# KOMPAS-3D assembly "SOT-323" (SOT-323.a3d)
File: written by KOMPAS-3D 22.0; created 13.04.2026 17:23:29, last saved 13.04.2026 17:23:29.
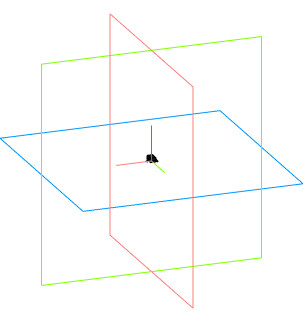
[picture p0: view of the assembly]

Document properties: Автор: Andrey; Полное имя файла: C:\Users\User1\Documents\SOT-323.a3d

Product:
- Component [assembly]: Document  | qty 1  | source file: Document.a3d
- Part/product: SOT-323
    Комментарий: SOT-323

Referenced files in C:\Users\User1\Documents\: Document.a3d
